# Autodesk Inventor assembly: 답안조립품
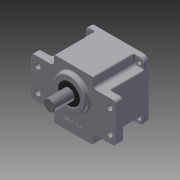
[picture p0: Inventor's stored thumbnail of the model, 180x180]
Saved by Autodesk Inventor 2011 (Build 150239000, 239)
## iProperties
Created: 2014-12
Part Number: 답안조립품
Document SubType Name: Assembly
Designer: Administrator
Author: Administrator
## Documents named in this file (12)
- C:\Documents and Settings\Administrator\바탕 화면\Inventor2급-장정숙\답안조립품.iam
- C:\Documents and Settings\Administrator\바탕 화면\Inventor2급-장정숙\본체.ipt
- C:\Documents and Settings\Administrator\바탕 화면\Inventor2급-장정숙\오일실 17x32x8.ipt
- C:\Documents and Settings\Administrator\바탕 화면\Inventor2급-장정숙\베어링 6003.ipt
- 베어링 6003.ipt
- C:\Documents and Settings\Administrator\바탕 화면\Inventor2급-장정숙\베어링 608.ipt
- 베어링 608.ipt
- C:\Documents and Settings\Administrator\바탕 화면\Inventor2급-장정숙\서브축.ipt
- C:\Documents and Settings\Administrator\바탕 화면\Inventor2급-장정숙\메인축.ipt
- C:\Documents and Settings\Administrator\바탕 화면\Inventor2급-장정숙\커버.ipt
- C:\Documents and Settings\Administrator\바탕 화면\Inventor2급-장정숙\오일실 8x22x7.ipt
- C:\Documents and Settings\Administrator\바탕 화면\Inventor2급-장정숙\M4x0.5x16.ipt
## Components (4 placed, 1 different names)
1. M4x0.5x12:1
2. M4x0.5x12:2
3. M4x0.5x12:3
4. M4x0.5x12:4
